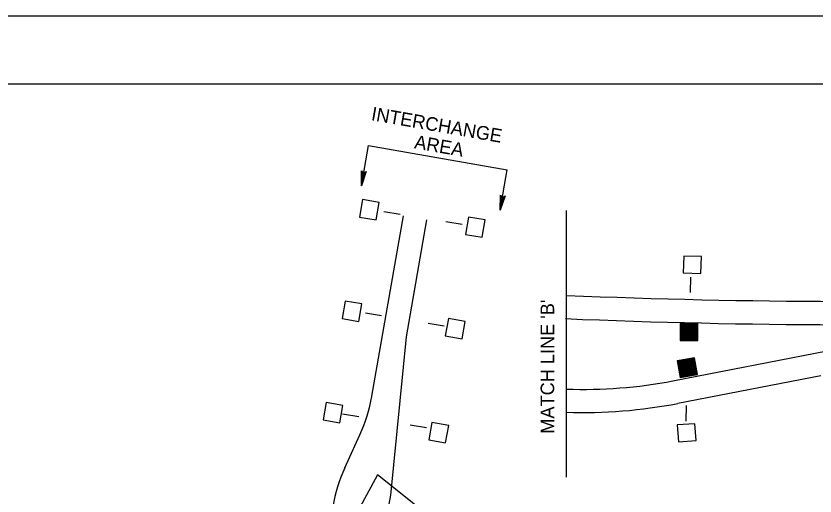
# Model space of a CAD drawing. Extents: x 640253 to 641999, y 298458 to 299646.
# Drawn here: x 641527.8 to 641704.3, y 299539.6 to 299645.6 of the extents above; entities that cross this region are included whole.
import ezdxf

# ---------------------------------------------------------------- set-up
doc = ezdxf.new("R2010")
doc.units = 0
for name, color, linetype in [('1', 7, 'Continuous'), ('2', 7, 'Continuous'), ('PLT-BNDY', 7, 'Continuous')]:
    doc.layers.add(name, color=color, linetype=linetype)

msp = doc.modelspace()

# ---------------------------------------------------------------- linework, layer by layer
at = {"layer": '1'}
msp.add_line((641134.31, 299630.63), (641920.31, 299630.63), dxfattribs=at)
at = {"layer": '2'}
for p, q in [((641604.1, 299608.07), (641605.66, 299616.99)), ((641605.66, 299616.99), (641636.34, 299611.63)), ((641634.77, 299602.71), (641636.34, 299611.63)), ((641606.45, 299561.61), (641613.42, 299601.46)), ((641609.07, 299602.45), (641612.66, 299601.86)), ((641649.42, 299543.72), (641649.42, 299602.62)), ((641614.05, 299574.76), (641618.56, 299600.56)), ((641622.76, 299600.19), (641626.35, 299599.6)), ((641676.79, 299584.52), (641676.87, 299587.96)), ((641604.99, 299580.02), (641608.58, 299579.43)), ((641618.84, 299577.75), (641622.43, 299577.16)), ((641610.58, 299539.79), (641614.05, 299574.76)), ((641672.93, 299565.02), (641707.01, 299571.63)), ((641674.04, 299560.09), (641705.59, 299566.17)), ((641675.83, 299556.13), (641675.91, 299559.57)), ((641599.94, 299557.77), (641603.53, 299557.18)), ((641614.92, 299555.31), (641618.51, 299554.71)), ((641600.44, 299545.81), (641603.79, 299553.1)), ((641591, 299427.89), (641610.58, 299539.79)), ((641610.58, 299539.79), (641610.58, 299539.79))]:
    msp.add_line(p, q, dxfattribs=at)
for points in [[(641605.04, 299611.11), (641604.8, 299611.04), (641604.1, 299608.07), (641605.04, 299611.11), (641605.2, 299611.25), (641604.1, 299608.07), (641604.49, 299611.09), (641604.28, 299611.23), (641604.1, 299608.07), (641604.15, 299611.42), (641604.28, 299611.23)], [(641635.71, 299605.75), (641635.47, 299605.67), (641634.77, 299602.71), (641635.71, 299605.75), (641635.87, 299605.88), (641634.77, 299602.71), (641635.15, 299605.73), (641634.95, 299605.87), (641634.77, 299602.71), (641634.83, 299606.06), (641634.95, 299605.87)], [(641674.52, 299573.95), (641678.42, 299573.95), (641678.42, 299577.7), (641674.52, 299577.7), (641674.52, 299573.95), (641678.36, 299577.62), (641674.59, 299577.62), (641674.59, 299574), (641678.36, 299574), (641678.36, 299577.56), (641674.66, 299577.56), (641674.66, 299574.07), (641678.28, 299574.07), (641678.27, 299577.47), (641674.73, 299577.47), (641674.73, 299574.13), (641678.21, 299574.13), (641678.21, 299577.41), (641674.8, 299577.41), (641674.8, 299574.19), (641678.13, 299574.19), (641678.12, 299577.34), (641674.87, 299577.34), (641674.86, 299574.25), (641678.07, 299574.26), (641678.04, 299577.27), (641674.94, 299577.27), (641674.93, 299574.31), (641678, 299574.33), (641677.98, 299577.2), (641675.01, 299577.2), (641674.98, 299574.39), (641677.91, 299574.41), (641677.91, 299577.11), (641675.09, 299577.12), (641675.06, 299574.44), (641677.81, 299574.49), (641677.82, 299577.05), (641675.17, 299577.05), (641675.13, 299574.51), (641677.73, 299574.55), (641677.73, 299576.99), (641675.25, 299576.97), (641675.21, 299574.55), (641677.64, 299574.61), (641677.64, 299576.92), (641675.34, 299576.89), (641675.29, 299575.79), (641675.29, 299574.61), (641677.57, 299574.69), (641677.54, 299576.82), (641675.42, 299576.78), (641675.38, 299574.69), (641677.48, 299574.76), (641677.45, 299576.74), (641675.52, 299576.68), (641675.48, 299574.78), (641677.35, 299574.83), (641677.33, 299576.61), (641675.66, 299576.57), (641675.6, 299574.91), (641677.21, 299574.94), (641677.19, 299576.51), (641675.81, 299576.45), (641675.74, 299575.02), (641675.74, 299575.02), (641677.06, 299575.07), (641677.05, 299576.36), (641675.95, 299576.32), (641675.88, 299575.15), (641676.91, 299575.21), (641676.92, 299576.2), (641676.09, 299576.19), (641676.05, 299575.31), (641676.75, 299575.34), (641676.72, 299576.08), (641676.25, 299576.05), (641676.23, 299575.44), (641676.57, 299575.47), (641676.57, 299575.92), (641676.43, 299575.95), (641676.41, 299575.59)], [(641674.53, 299565.77), (641678.37, 299566.45), (641677.71, 299570.14), (641673.88, 299569.46), (641674.53, 299565.77), (641677.67, 299570.06), (641673.95, 299569.41), (641674.58, 299565.84), (641678.29, 299566.49), (641677.68, 299569.99), (641674.04, 299569.35), (641674.64, 299565.91), (641678.21, 299566.54), (641677.61, 299569.89), (641674.12, 299569.27), (641674.7, 299565.98), (641678.13, 299566.59), (641677.56, 299569.82), (641674.2, 299569.23), (641674.76, 299566.05), (641678.04, 299566.64), (641677.48, 299569.74), (641674.28, 299569.18), (641674.81, 299566.12), (641677.96, 299566.7), (641677.42, 299569.65), (641674.36, 299569.11), (641674.86, 299566.2), (641677.88, 299566.75), (641677.37, 299569.57), (641674.44, 299569.06), (641674.91, 299566.29), (641677.78, 299566.81), (641677.32, 299569.47), (641674.54, 299569), (641674.97, 299566.35), (641677.67, 299566.87), (641677.24, 299569.4), (641674.63, 299568.94), (641675.03, 299566.43), (641677.59, 299566.92), (641677.16, 299569.33), (641674.72, 299568.88), (641675.1, 299566.48), (641677.49, 299566.97), (641677.08, 299569.24), (641674.82, 299568.8), (641674.96, 299567.71), (641675.17, 299566.56), (641677.4, 299567.03), (641677, 299569.12), (641674.92, 299568.72), (641675.24, 299566.65), (641677.3, 299567.09), (641676.93, 299569.03), (641675.04, 299568.64), (641675.33, 299566.76), (641677.17, 299567.13), (641676.84, 299568.88), (641675.19, 299568.55), (641675.42, 299566.9), (641677, 299567.21), (641676.71, 299568.75), (641675.36, 299568.46), (641675.54, 299567.04), (641675.55, 299567.04), (641676.83, 299567.32), (641676.6, 299568.59), (641675.52, 299568.36), (641675.66, 299567.19), (641676.65, 299567.43), (641676.49, 299568.41), (641675.68, 299568.24), (641675.8, 299567.37), (641676.48, 299567.52), (641676.32, 299568.25), (641675.87, 299568.14), (641675.95, 299567.54), (641676.29, 299567.63), (641676.21, 299568.07), (641676.06, 299568.07), (641676.1, 299567.72)], [(641635.54, 299521.92), (641607.68, 299544.27), (641603.36, 299536.2)]]:
    msp.add_lwpolyline(points, dxfattribs=at)
for points in [[(641607.39, 299600.56), (641608.06, 299604.4), (641604.37, 299605.05), (641603.7, 299601.21)], [(641630.78, 299596.73), (641631.45, 299600.57), (641627.76, 299601.21), (641627.09, 299597.37)], [(641675.22, 299588.85), (641679.12, 299588.71), (641679.25, 299592.46), (641675.35, 299592.59)], [(641603.56, 299578.16), (641604.23, 299582), (641600.54, 299582.65), (641599.87, 299578.81)], [(641626.35, 299574.32), (641627.02, 299578.16), (641623.33, 299578.81), (641622.65, 299574.97)], [(641599.32, 299555.76), (641599.99, 299559.6), (641596.3, 299560.24), (641595.63, 299556.4)], [(641622.71, 299551.32), (641623.39, 299555.16), (641619.69, 299555.8), (641619.02, 299551.96)], [(641674.17, 299551.55), (641678.05, 299551.81), (641677.79, 299555.55), (641673.9, 299555.28)]]:
    msp.add_lwpolyline(points, close=True, dxfattribs=at)
for centre, radius, start, end in [((641713.53, 301122.08), 1539.51, 267.61256, 276.52429), ((641713.53, 301122.08), 1544.66, 267.61256, 276.52429), ((641653.13, 299667.27), 104.14, 267.9574, 280.9617), ((641572.25, 299567.59), 34.71, 335.3192, 350.0612), ((641653.23, 299667.41), 109.37, 268.0001, 280.9651), ((641631.97, 299531.3), 34.71, 155.2901, 170.0975)]:
    msp.add_arc(centre, radius, start, end, dxfattribs=at)
at = {"layer": 'PLT-BNDY'}
msp.add_lwpolyline([(641094.31, 299645.63), (641935.31, 299645.63), (641935.31, 299051.63), (641094.31, 299051.63)], close=True, dxfattribs=at)

# ---------------------------------------------------------------- texts
at = {"layer": '2'}
for s, rotation, p in [('INTERCHANGE', 350.0808, (641606.14, 299622.63)), ('AREA', 350.0808, (641615.65, 299616.4)), ("MATCH LINE 'B'", 90, (641646.7, 299553.34))]:
    msp.add_text(s, height=3, rotation=rotation, dxfattribs=at).set_placement(p)

doc.saveas('drawing.dxf')
